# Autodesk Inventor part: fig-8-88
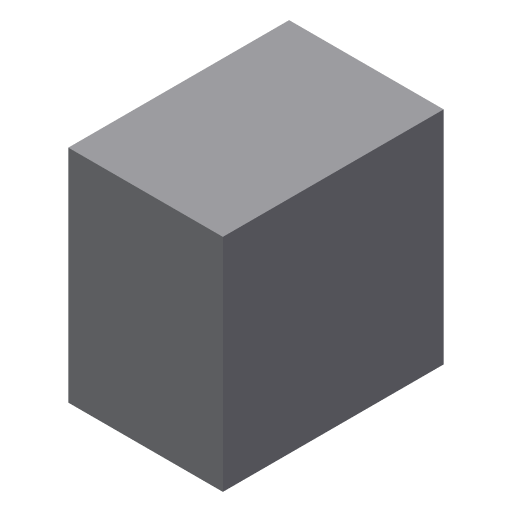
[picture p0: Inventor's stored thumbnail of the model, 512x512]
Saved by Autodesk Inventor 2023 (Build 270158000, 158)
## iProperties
Created: 2009-04
Part Number: fig-8-88
Document SubType Name: Modeling
Designer: Sham
Density: 1 g/cm^3
Material: Generic
Appearance: Default
Author: Sham
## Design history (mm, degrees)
sketch "Sketch5"
  geometry: L1 (14, -20)-(0, -20); L2 (0, -20)-(0, 0); L3 (0, 0)-(14, 0); L4 (14, 0)-(14, -20)
  constraints: 8 end point
extrude "Extrusion2" new body sketch "Sketch5" distance "d3" = 20; taper "d4" = 0 deg
sketch "Sketch6"
  geometry: L1 (-5, 12)-(17, 7)
  constraints: 2 end point
split "Split8" sketch "Sketch6"
  body "Solid2"
body "Solid3"
body "Solid4"
